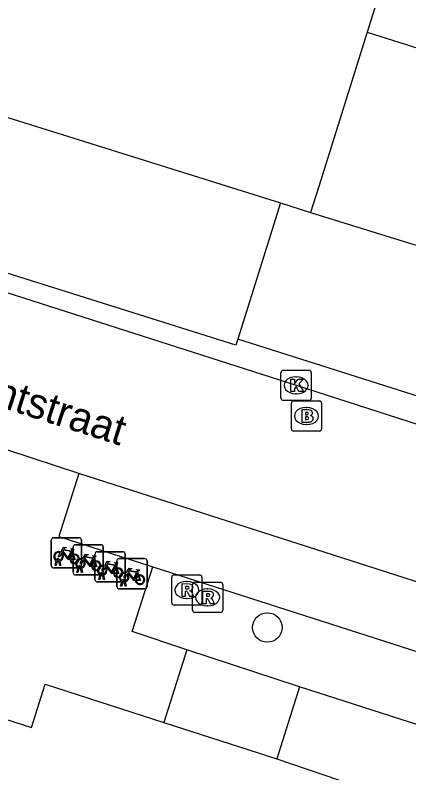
# Model space of a CAD drawing. Extents: x 160676 to 161153, y 383244 to 383713.
# Drawn here: x 160900.48 to 160913.52, y 383387.79 to 383412.86 of the extents above; entities that cross this region are included whole.
import ezdxf

# ---------------------------------------------------------------- set-up
doc = ezdxf.new("R2010")
doc.units = 0
for name, color, linetype in [('IMGEO_Boom', 7, 'Continuous'), ('IMGEO_Brandkraan', 7, 'Continuous'), ('IMGEO_Fietsenrek', 7, 'Continuous'), ('IMGEO_Hek', 7, 'Continuous'), ('IMGEO_Kolk', 7, 'Continuous'), ('IMGEO_Openbare_ruimte_label', 7, 'Continuous'), ('IMGEO_Pand', 7, 'Continuous'), ('IMGEO_Parkeervlak_open', 7, 'Continuous'), ('IMGEO_Rijbaan_lokaal_open', 7, 'Continuous'), ('IMGEO_Rioolput', 7, 'Continuous'), ('IMGEO_Voetpad_op_trap', 7, 'Continuous'), ('IMGEO_Voetpad_open', 7, 'Continuous')]:
    doc.layers.add(name, color=color, linetype=linetype)

msp = doc.modelspace()

# ---------------------------------------------------------------- linework, layer by layer
at = {"layer": 'IMGEO_Boom'}
msp.add_circle((160908.826, 383392.602), 0.489, dxfattribs=at)
at = {"layer": 'IMGEO_Brandkraan'}
for p, q in [((160909.699, 383400.1), (160910.551, 383400.1)), ((160909.624, 383399.174), (160909.624, 383400.026)), ((160910.112, 383399.88), (160910.137, 383399.88)), ((160910.625, 383400.026), (160910.625, 383399.174)), ((160910.551, 383399.1), (160909.699, 383399.1)), ((160910.135, 383399.32), (160910.11, 383399.32))]:
    msp.add_line(p, q, dxfattribs=at)
for points in [[(160909.699, 383400.1), (160910.551, 383400.1)], [(160909.624, 383399.174), (160909.624, 383400.026)], [(160910.625, 383400.026), (160910.625, 383399.174)], [(160909.972, 383399.8), (160909.972, 383399.4), (160910.185, 383399.4)], [(160910.203, 383399.8), (160909.972, 383399.8)], [(160910.151, 383399.719), (160910.097, 383399.719), (160910.097, 383399.643)], [(160910.097, 383399.643), (160910.15, 383399.643)], [(160910.159, 383399.567), (160910.097, 383399.567), (160910.097, 383399.486)], [(160910.097, 383399.486), (160910.159, 383399.486)], [(160910.551, 383399.1), (160909.699, 383399.1)]]:
    msp.add_lwpolyline(points, dxfattribs=at)
for centre, radius, start, end in [((160909.701, 383400.024), 0.0765, 91.552, 178.448), ((160909.701, 383400.024), 0.0765, 91.552, 178.448), ((160910.549, 383400.024), 0.0765, 1.552, 88.448), ((160910.549, 383400.024), 0.0765, 1.552, 88.448), ((160910.152, 383399.681), 0.0379, 267.8285, 90.9355), ((160910.207, 383399.655), 0.145, 59.4692, 91.5367), ((160910.232, 383399.702), 0.0922, 285.5137, 58.1501), ((160910.237, 383399.51), 0.105, 301.3115, 78.989), ((160910.16, 383399.526), 0.0404, 269.8759, 90.5077), ((160910.191, 383399.651), 0.251, 268.6676, 293.5347), ((160909.701, 383399.176), 0.0765, 181.552, 268.448), ((160909.701, 383399.176), 0.0765, 181.552, 268.448), ((160910.549, 383399.176), 0.0765, 271.552, 358.448), ((160910.549, 383399.176), 0.0765, 271.552, 358.448)]:
    msp.add_arc(centre, radius, start, end, dxfattribs=at)
for centre, major_axis, ratio, start_param, end_param in [((160910.111, 383399.6), (-0.387, 0.002), 0.722429, 4.712389, 7.853982), ((160910.136, 383399.6), (-0.39, 0.002), 0.717154, 1.570796, 4.712389)]:
    msp.add_ellipse(centre, major_axis=major_axis, ratio=ratio, start_param=start_param, end_param=end_param, dxfattribs=at)
at = {"layer": 'IMGEO_Fietsenrek'}
for p, q in [((160901.748, 383395.571), (160902.589, 383395.571)), ((160902.589, 383395.571), (160901.748, 383395.571)), ((160901.673, 383394.646), (160901.673, 383395.487)), ((160901.673, 383395.487), (160901.673, 383394.646)), ((160902.471, 383395.341), (160903.312, 383395.341)), ((160903.312, 383395.341), (160902.471, 383395.341)), ((160902.673, 383395.496), (160902.673, 383394.655)), ((160902.673, 383394.655), (160902.673, 383395.496)), ((160902.36, 383395.12), (160902.396, 383395.025)), ((160902.396, 383394.416), (160902.396, 383395.257)), ((160902.396, 383395.257), (160902.396, 383394.416)), ((160903.195, 383395.11), (160904.036, 383395.11)), ((160904.036, 383395.11), (160903.195, 383395.11)), ((160903.396, 383395.266), (160903.396, 383394.425)), ((160903.396, 383394.425), (160903.396, 383395.266)), ((160901.8, 383394.655), (160901.839, 383394.815)), ((160901.911, 383394.827), (160901.91, 383394.831)), ((160901.942, 383394.838), (160901.943, 383394.831)), ((160903.083, 383394.89), (160903.119, 383394.795)), ((160903.12, 383394.185), (160903.12, 383395.026)), ((160903.12, 383395.026), (160903.12, 383394.185)), ((160903.918, 383394.88), (160904.759, 383394.88)), ((160904.759, 383394.88), (160903.918, 383394.88)), ((160904.12, 383395.035), (160904.12, 383394.194)), ((160904.12, 383394.194), (160904.12, 383395.035)), ((160902.598, 383394.571), (160901.757, 383394.571)), ((160901.757, 383394.571), (160902.598, 383394.571)), ((160901.834, 383394.655), (160901.8, 383394.655)), ((160901.869, 383394.803), (160901.834, 383394.655)), ((160901.952, 383394.655), (160901.918, 383394.797)), ((160901.95, 383394.801), (160901.985, 383394.655)), ((160901.985, 383394.655), (160901.952, 383394.655)), ((160902.523, 383394.425), (160902.562, 383394.585)), ((160902.592, 383394.573), (160902.557, 383394.425)), ((160902.634, 383394.597), (160902.633, 383394.601)), ((160902.675, 383394.425), (160902.641, 383394.567)), ((160902.665, 383394.608), (160902.666, 383394.601)), ((160902.673, 383394.571), (160902.708, 383394.425)), ((160903.807, 383394.659), (160903.843, 383394.564)), ((160903.843, 383393.955), (160903.843, 383394.796)), ((160903.843, 383394.796), (160903.843, 383393.955)), ((160904.843, 383394.805), (160904.843, 383393.964)), ((160904.843, 383393.964), (160904.843, 383394.805)), ((160903.321, 383394.341), (160902.48, 383394.341)), ((160902.48, 383394.341), (160903.321, 383394.341)), ((160902.557, 383394.425), (160902.523, 383394.425)), ((160902.708, 383394.425), (160902.675, 383394.425)), ((160903.247, 383394.194), (160903.286, 383394.354)), ((160903.316, 383394.342), (160903.281, 383394.194)), ((160903.358, 383394.366), (160903.357, 383394.37)), ((160903.399, 383394.194), (160903.365, 383394.336)), ((160903.389, 383394.377), (160903.39, 383394.37)), ((160903.397, 383394.34), (160903.432, 383394.194)), ((160904.53, 383394.429), (160904.566, 383394.334)), ((160904.045, 383394.11), (160903.204, 383394.11)), ((160903.204, 383394.11), (160904.045, 383394.11)), ((160903.281, 383394.194), (160903.247, 383394.194)), ((160903.432, 383394.194), (160903.399, 383394.194)), ((160903.97, 383393.964), (160904.009, 383394.124)), ((160904.039, 383394.112), (160904.004, 383393.964)), ((160904.081, 383394.136), (160904.08, 383394.14)), ((160904.122, 383393.964), (160904.088, 383394.106)), ((160904.112, 383394.147), (160904.113, 383394.14)), ((160904.12, 383394.11), (160904.155, 383393.964)), ((160904.768, 383393.88), (160903.927, 383393.88)), ((160903.927, 383393.88), (160904.768, 383393.88)), ((160904.004, 383393.964), (160903.97, 383393.964)), ((160904.155, 383393.964), (160904.122, 383393.964))]:
    msp.add_line(p, q, dxfattribs=at)
for points in [[(160902.007, 383395.045), (160901.955, 383394.955), (160901.915, 383394.93), (160901.916, 383394.977), (160901.971, 383395.071)], [(160901.986, 383395.097), (160902.081, 383395.261), (160902.167, 383395.247), (160902.169, 383395.238), (160902.113, 383395.227), (160902.086, 383395.182), (160902.342, 383395.141)], [(160902.282, 383394.853), (160902.232, 383394.853), (160902.041, 383395.104), (160902.022, 383395.072)], [(160902.329, 383395.116), (160902.072, 383395.157), (160902.055, 383395.128), (160902.222, 383394.908), (160902.329, 383395.116)], [(160902.377, 383395.018), (160902.347, 383395.095), (160902.238, 383394.877), (160902.281, 383394.877)], [(160902.342, 383395.141), (160902.367, 383395.19), (160902.361, 383395.194), (160902.338, 383395.198), (160902.326, 383395.205), (160902.325, 383395.208), (160902.327, 383395.213), (160902.422, 383395.198), (160902.424, 383395.188), (160902.414, 383395.175), (160902.402, 383395.169), (160902.388, 383395.175), (160902.36, 383395.12)], [(160902.311, 383394.877), (160902.431, 383394.876), (160902.387, 383394.99)], [(160902.407, 383394.997), (160902.462, 383394.852), (160902.312, 383394.852)], [(160902.73, 383394.815), (160902.678, 383394.725), (160902.638, 383394.7), (160902.639, 383394.747), (160902.694, 383394.841)], [(160902.709, 383394.867), (160902.804, 383395.031), (160902.89, 383395.017), (160902.892, 383395.008), (160902.836, 383394.997), (160902.809, 383394.952), (160903.065, 383394.911)], [(160903.005, 383394.623), (160902.955, 383394.623), (160902.764, 383394.874), (160902.745, 383394.842)], [(160903.052, 383394.886), (160902.795, 383394.927), (160902.778, 383394.898), (160902.945, 383394.678), (160903.052, 383394.886)], [(160903.1, 383394.788), (160903.07, 383394.865), (160902.961, 383394.647), (160903.004, 383394.647)], [(160903.065, 383394.911), (160903.09, 383394.96), (160903.084, 383394.964), (160903.061, 383394.968), (160903.049, 383394.975), (160903.048, 383394.978), (160903.05, 383394.983), (160903.145, 383394.968), (160903.147, 383394.958), (160903.137, 383394.945), (160903.125, 383394.939), (160903.111, 383394.945), (160903.083, 383394.89)], [(160903.034, 383394.647), (160903.154, 383394.646), (160903.11, 383394.76)], [(160903.13, 383394.767), (160903.185, 383394.622), (160903.035, 383394.622)], [(160903.454, 383394.584), (160903.402, 383394.494), (160903.362, 383394.469), (160903.363, 383394.516), (160903.418, 383394.61)], [(160903.433, 383394.636), (160903.528, 383394.8), (160903.614, 383394.786), (160903.616, 383394.777), (160903.56, 383394.766), (160903.533, 383394.721), (160903.789, 383394.68)], [(160903.729, 383394.392), (160903.679, 383394.392), (160903.488, 383394.643), (160903.469, 383394.611)], [(160903.776, 383394.655), (160903.519, 383394.696), (160903.502, 383394.667), (160903.669, 383394.447), (160903.776, 383394.655)], [(160903.824, 383394.557), (160903.794, 383394.634), (160903.685, 383394.416), (160903.728, 383394.416)], [(160903.789, 383394.68), (160903.814, 383394.729), (160903.808, 383394.733), (160903.785, 383394.737), (160903.773, 383394.744), (160903.772, 383394.747), (160903.774, 383394.752), (160903.869, 383394.737), (160903.871, 383394.727), (160903.861, 383394.714), (160903.849, 383394.708), (160903.835, 383394.714), (160903.807, 383394.659)], [(160904.156, 383394.406), (160904.251, 383394.57), (160904.337, 383394.556), (160904.339, 383394.547), (160904.283, 383394.536), (160904.256, 383394.491), (160904.512, 383394.45)], [(160903.758, 383394.416), (160903.878, 383394.415), (160903.834, 383394.529)], [(160903.854, 383394.536), (160903.909, 383394.391), (160903.759, 383394.391)], [(160904.177, 383394.354), (160904.125, 383394.264), (160904.085, 383394.239), (160904.086, 383394.286), (160904.141, 383394.38)], [(160904.452, 383394.162), (160904.402, 383394.162), (160904.211, 383394.413), (160904.192, 383394.381)], [(160904.499, 383394.425), (160904.242, 383394.466), (160904.225, 383394.437), (160904.392, 383394.217), (160904.499, 383394.425)], [(160904.547, 383394.327), (160904.517, 383394.404), (160904.408, 383394.186), (160904.451, 383394.186)], [(160904.512, 383394.45), (160904.537, 383394.499), (160904.531, 383394.503), (160904.508, 383394.507), (160904.496, 383394.514), (160904.495, 383394.517), (160904.497, 383394.522), (160904.592, 383394.507), (160904.594, 383394.497), (160904.584, 383394.484), (160904.572, 383394.478), (160904.558, 383394.484), (160904.53, 383394.429)], [(160904.481, 383394.186), (160904.601, 383394.185), (160904.557, 383394.299)], [(160904.577, 383394.306), (160904.632, 383394.161), (160904.482, 383394.161)]]:
    msp.add_lwpolyline(points, dxfattribs=at)
for centre, radius, start, end in [((160901.751, 383395.493), 0.0779, 92.4484, 184.2845), ((160901.751, 383395.493), 0.0779, 92.4484, 184.2845), ((160902.595, 383395.493), 0.0779, 2.4484, 94.2845), ((160902.595, 383395.493), 0.0779, 2.4484, 94.2845), ((160902.474, 383395.263), 0.0779, 92.4484, 184.2845), ((160902.474, 383395.263), 0.0779, 92.4484, 184.2845), ((160903.318, 383395.263), 0.0779, 2.4484, 94.2845), ((160903.318, 383395.263), 0.0779, 2.4484, 94.2845), ((160901.913, 383394.956), 0.159, 62.6766, 242.1369), ((160901.913, 383394.956), 0.129, 63.3192, 238.903), ((160901.913, 383394.956), 0.159, 283.5766, 46.6042), ((160903.198, 383395.032), 0.0779, 92.4484, 184.2845), ((160903.198, 383395.032), 0.0779, 92.4484, 184.2845), ((160904.042, 383395.032), 0.0779, 2.4484, 94.2845), ((160904.042, 383395.032), 0.0779, 2.4484, 94.2845), ((160901.893, 383394.827), 0.0499, 12.8025, 158.6934), ((160901.893, 383394.827), 0.0174, 12.8025, 163.4502), ((160901.913, 383394.956), 0.129, 253.415, 269.0204), ((160901.913, 383394.956), 0.129, 283.6043, 43.4302), ((160902.44, 383394.872), 0.159, 113.3408, 178.3217), ((160902.44, 383394.872), 0.159, 187.0065, 105.7708), ((160902.44, 383394.872), 0.129, 113.923, 177.9556), ((160902.44, 383394.872), 0.129, 188.6715, 104.5883), ((160902.636, 383394.726), 0.159, 62.6766, 242.1369), ((160902.636, 383394.726), 0.129, 63.3192, 238.903), ((160902.636, 383394.726), 0.129, 283.6043, 43.4302), ((160902.636, 383394.726), 0.159, 283.5766, 46.6042), ((160903.921, 383394.802), 0.0779, 92.4484, 184.2845), ((160903.921, 383394.802), 0.0779, 92.4484, 184.2845), ((160904.765, 383394.802), 0.0779, 2.4484, 94.2845), ((160904.765, 383394.802), 0.0779, 2.4484, 94.2845), ((160901.751, 383394.649), 0.0779, 182.4484, 274.2845), ((160901.751, 383394.649), 0.0779, 182.4484, 274.2845), ((160901.913, 383394.956), 0.159, 253.9967, 271.7867), ((160902.616, 383394.597), 0.0499, 12.8025, 158.6934), ((160902.636, 383394.726), 0.159, 253.9967, 271.7867), ((160902.595, 383394.649), 0.0779, 272.4484, 4.2845), ((160902.595, 383394.649), 0.0779, 272.4484, 4.2845), ((160902.616, 383394.597), 0.0174, 12.8025, 163.4502), ((160902.636, 383394.726), 0.129, 253.415, 269.0204), ((160903.163, 383394.642), 0.159, 113.3408, 178.3217), ((160903.163, 383394.642), 0.159, 187.0065, 105.7708), ((160903.163, 383394.642), 0.129, 113.923, 177.9556), ((160903.163, 383394.642), 0.129, 188.6715, 104.5883), ((160903.36, 383394.495), 0.159, 62.6766, 242.1369), ((160903.36, 383394.495), 0.129, 63.3192, 238.903), ((160903.36, 383394.495), 0.129, 283.6043, 43.4302), ((160903.36, 383394.495), 0.159, 283.5766, 46.6042), ((160903.887, 383394.411), 0.159, 187.0065, 105.7708), ((160902.474, 383394.419), 0.0779, 182.4484, 274.2845), ((160902.474, 383394.419), 0.0779, 182.4484, 274.2845), ((160903.34, 383394.366), 0.0499, 12.8025, 158.6934), ((160903.36, 383394.495), 0.159, 253.9967, 271.7867), ((160903.318, 383394.419), 0.0779, 272.4484, 4.2845), ((160903.318, 383394.419), 0.0779, 272.4484, 4.2845), ((160903.34, 383394.366), 0.0174, 12.8025, 163.4502), ((160903.36, 383394.495), 0.129, 253.415, 269.0204), ((160903.887, 383394.411), 0.159, 113.3408, 178.3217), ((160903.887, 383394.411), 0.129, 113.923, 177.9556), ((160903.887, 383394.411), 0.129, 188.6715, 104.5883), ((160904.083, 383394.265), 0.159, 62.6766, 242.1369), ((160904.083, 383394.265), 0.129, 63.3192, 238.903), ((160904.083, 383394.265), 0.129, 283.6043, 43.4302), ((160904.083, 383394.265), 0.159, 283.5766, 46.6042), ((160904.61, 383394.181), 0.159, 113.3408, 178.3217), ((160904.61, 383394.181), 0.159, 187.0065, 105.7708), ((160904.61, 383394.181), 0.129, 188.6715, 104.5883), ((160903.198, 383394.188), 0.0779, 182.4484, 274.2845), ((160903.198, 383394.188), 0.0779, 182.4484, 274.2845), ((160904.063, 383394.136), 0.0499, 12.8025, 158.6934), ((160904.083, 383394.265), 0.159, 253.9967, 271.7867), ((160904.042, 383394.188), 0.0779, 272.4484, 4.2845), ((160904.042, 383394.188), 0.0779, 272.4484, 4.2845), ((160904.063, 383394.136), 0.0174, 12.8025, 163.4502), ((160904.083, 383394.265), 0.129, 253.415, 269.0204), ((160904.61, 383394.181), 0.129, 113.923, 177.9556), ((160903.921, 383393.958), 0.0779, 182.4484, 274.2845), ((160903.921, 383393.958), 0.0779, 182.4484, 274.2845), ((160904.765, 383393.958), 0.0779, 272.4484, 4.2845), ((160904.765, 383393.958), 0.0779, 272.4484, 4.2845)]:
    msp.add_arc(centre, radius, start, end, dxfattribs=at)
at = {"layer": 'IMGEO_Hek'}
msp.add_lwpolyline([(160947.221, 383389.66), (160907.851, 383402.14)], dxfattribs=at)
at = {"layer": 'IMGEO_Kolk'}
for p, q in [((160909.355, 383401.115), (160910.207, 383401.115)), ((160909.28, 383400.189), (160909.28, 383401.041)), ((160909.768, 383400.895), (160909.793, 383400.895)), ((160910.281, 383401.041), (160910.281, 383400.189)), ((160909.791, 383400.335), (160909.766, 383400.335)), ((160910.207, 383400.115), (160909.355, 383400.115))]:
    msp.add_line(p, q, dxfattribs=at)
for points in [[(160909.355, 383401.115), (160910.207, 383401.115)], [(160909.28, 383400.189), (160909.28, 383401.041)], [(160910.281, 383401.041), (160910.281, 383400.189)], [(160909.601, 383400.815), (160909.724, 383400.815), (160909.724, 383400.664), (160909.854, 383400.815), (160910.018, 383400.815), (160909.872, 383400.664), (160910.025, 383400.415), (160909.873, 383400.415), (160909.788, 383400.579), (160909.724, 383400.512), (160909.724, 383400.415), (160909.601, 383400.415), (160909.601, 383400.815)], [(160910.207, 383400.115), (160909.355, 383400.115)]]:
    msp.add_lwpolyline(points, dxfattribs=at)
for centre, start, end in [((160909.357, 383401.039), 91.552, 178.448), ((160909.357, 383401.039), 91.552, 178.448), ((160910.205, 383401.039), 1.552, 88.448), ((160910.205, 383401.039), 1.552, 88.448), ((160909.357, 383400.191), 181.552, 268.448), ((160909.357, 383400.191), 181.552, 268.448), ((160910.205, 383400.191), 271.552, 358.448), ((160910.205, 383400.191), 271.552, 358.448)]:
    msp.add_arc(centre, 0.0765, start, end, dxfattribs=at)
for centre, major_axis, ratio, start_param, end_param in [((160909.767, 383400.615), (-0.387, 0.002), 0.722429, 4.712389, 7.853982), ((160909.792, 383400.615), (-0.39, 0.002), 0.717154, 1.570796, 4.712389)]:
    msp.add_ellipse(centre, major_axis=major_axis, ratio=ratio, start_param=start_param, end_param=end_param, dxfattribs=at)
at = {"layer": 'IMGEO_Pand'}
for points in [[(160907.851, 383402.14), (160907.79, 383401.946), (160898.585, 383404.834), (160900.061, 383409.537), (160909.266, 383406.649)], [(160909.266, 383406.649), (160907.851, 383402.14)], [(160886.606, 383395.503), (160896.283, 383392.391), (160895.823, 383390.963), (160901.015, 383389.295), (160901.475, 383390.722), (160905.053, 383389.568), (160905.398, 383389.462)], [(160905.398, 383389.462), (160909.143, 383388.26)], [(160909.143, 383388.26), (160911.188, 383387.556), (160910.671, 383385.909)]]:
    msp.add_lwpolyline(points, dxfattribs=at)
at = {"layer": 'IMGEO_Parkeervlak_open'}
for points in [[(160913.38, 383416.284), (160912.129, 383412.296)], [(160909.266, 383406.649), (160910.259, 383406.337)], [(160947.221, 383389.66), (160907.851, 383402.14)], [(160905.032, 383394.612), (160936.244, 383384.606), (160952.13, 383379.495)]]:
    msp.add_lwpolyline(points, dxfattribs=at)
at = {"layer": 'IMGEO_Rijbaan_lokaal_open'}
for points in [[(160912.129, 383412.296), (160910.529, 383407.197), (160910.259, 383406.337)], [(160912.129, 383412.296), (160949.567, 383400.481)], [(160887.438, 383407.737), (160890.968, 383406.604), (160893.121, 383405.949), (160909.781, 383400.615), (160922.621, 383396.479), (160938.323, 383391.448), (160946.431, 383388.877)], [(160910.259, 383406.337), (160952.446, 383393.288)], [(160902.588, 383397.698), (160899.445, 383398.723)], [(160953.275, 383381.428), (160937.803, 383386.409), (160902.588, 383397.698)]]:
    msp.add_lwpolyline(points, dxfattribs=at)
at = {"layer": 'IMGEO_Rioolput'}
for p, q in [((160905.737, 383394.342), (160906.589, 383394.342)), ((160905.662, 383393.416), (160905.662, 383394.268)), ((160906.15, 383394.122), (160906.175, 383394.122)), ((160906.424, 383394.098), (160907.276, 383394.098)), ((160906.663, 383394.268), (160906.663, 383393.416)), ((160906.349, 383393.172), (160906.349, 383394.024)), ((160906.837, 383393.878), (160906.862, 383393.878)), ((160907.35, 383394.024), (160907.35, 383393.172)), ((160906.173, 383393.562), (160906.148, 383393.562)), ((160906.589, 383393.342), (160905.737, 383393.342)), ((160906.86, 383393.318), (160906.835, 383393.318)), ((160907.276, 383393.098), (160906.424, 383393.098))]:
    msp.add_line(p, q, dxfattribs=at)
for points in [[(160905.737, 383394.342), (160906.589, 383394.342)], [(160905.662, 383393.416), (160905.662, 383394.268)], [(160906.424, 383394.098), (160907.276, 383394.098)], [(160906.663, 383394.268), (160906.663, 383393.416)], [(160906.251, 383394.04), (160905.999, 383394.042), (160905.999, 383393.642)], [(160906.177, 383393.961), (160906.123, 383393.961), (160906.123, 383393.88)], [(160906.123, 383393.88), (160906.175, 383393.88)], [(160906.349, 383393.172), (160906.349, 383394.024)], [(160907.35, 383394.024), (160907.35, 383393.172)], [(160905.999, 383393.642), (160906.123, 383393.642), (160906.123, 383393.804), (160906.134, 383393.804)], [(160906.181, 383393.775), (160906.252, 383393.642), (160906.392, 383393.642), (160906.327, 383393.768)], [(160906.938, 383393.796), (160906.686, 383393.798), (160906.686, 383393.398)], [(160906.686, 383393.398), (160906.81, 383393.398), (160906.81, 383393.56), (160906.821, 383393.56)], [(160906.864, 383393.717), (160906.81, 383393.717), (160906.81, 383393.636)], [(160906.81, 383393.636), (160906.862, 383393.636)], [(160906.589, 383393.342), (160905.737, 383393.342)], [(160906.868, 383393.531), (160906.939, 383393.398), (160907.079, 383393.398), (160907.014, 383393.524)], [(160907.276, 383393.098), (160906.424, 383393.098)]]:
    msp.add_lwpolyline(points, dxfattribs=at)
for centre, radius, start, end in [((160905.739, 383394.266), 0.0765, 91.552, 178.448), ((160905.739, 383394.266), 0.0765, 91.552, 178.448), ((160906.587, 383394.266), 0.0765, 1.552, 88.448), ((160906.587, 383394.266), 0.0765, 1.552, 88.448), ((160906.426, 383394.022), 0.0765, 91.552, 178.448), ((160906.426, 383394.022), 0.0765, 91.552, 178.448), ((160907.274, 383394.022), 0.0765, 1.552, 88.448), ((160907.274, 383394.022), 0.0765, 1.552, 88.448), ((160906.159, 383394.069), 0.19, 274.7715, 282.9687), ((160906.183, 383393.865), 0.0964, 77.0061, 93.1865), ((160906.197, 383393.922), 0.0378, 276.6634, 79.6772), ((160906.25, 383393.93), 0.109, 350.3612, 89.416), ((160906.248, 383393.93), 0.112, 277.5842, 350.9817), ((160906.232, 383393.715), 0.108, 29.5134, 73.7905), ((160906.133, 383393.751), 0.0533, 26.0293, 88.6989), ((160906.82, 383393.507), 0.0533, 26.0293, 88.6989), ((160906.846, 383393.825), 0.19, 274.7715, 282.9687), ((160906.87, 383393.621), 0.0964, 77.0061, 93.1865), ((160906.884, 383393.678), 0.0378, 276.6634, 79.6772), ((160906.937, 383393.686), 0.109, 350.3612, 89.416), ((160906.935, 383393.686), 0.112, 277.5842, 350.9817), ((160906.919, 383393.471), 0.108, 29.5134, 73.7905), ((160905.739, 383393.418), 0.0765, 181.552, 268.448), ((160905.739, 383393.418), 0.0765, 181.552, 268.448), ((160906.587, 383393.418), 0.0765, 271.552, 358.448), ((160906.587, 383393.418), 0.0765, 271.552, 358.448), ((160906.426, 383393.174), 0.0765, 181.552, 268.448), ((160906.426, 383393.174), 0.0765, 181.552, 268.448), ((160907.274, 383393.174), 0.0765, 271.552, 358.448), ((160907.274, 383393.174), 0.0765, 271.552, 358.448)]:
    msp.add_arc(centre, radius, start, end, dxfattribs=at)
for centre, major_axis, ratio, start_param, end_param in [((160906.149, 383393.842), (-0.387, 0.002), 0.722429, 4.712389, 7.853982), ((160906.174, 383393.842), (-0.39, 0.002), 0.717154, 1.570796, 4.712389), ((160906.836, 383393.598), (-0.387, 0.002), 0.722429, 4.712389, 7.853982), ((160906.861, 383393.598), (-0.39, 0.002), 0.717154, 1.570796, 4.712389)]:
    msp.add_ellipse(centre, major_axis=major_axis, ratio=ratio, start_param=start_param, end_param=end_param, dxfattribs=at)
at = {"layer": 'IMGEO_Voetpad_op_trap'}
msp.add_lwpolyline([(160909.89, 383390.636), (160906.167, 383391.864)], dxfattribs=at)
at = {"layer": 'IMGEO_Voetpad_open'}
for points in [[(160902.588, 383397.698), (160901.917, 383395.611), (160905.032, 383394.612)], [(160906.167, 383391.864), (160904.349, 383392.464), (160905.032, 383394.612)], [(160906.167, 383391.864), (160905.398, 383389.462)], [(160909.89, 383390.636), (160909.143, 383388.26)], [(160942.548, 383380.163), (160909.89, 383390.636)]]:
    msp.add_lwpolyline(points, dxfattribs=at)

# ---------------------------------------------------------------- texts
at = {"layer": 'IMGEO_Openbare_ruimte_label'}
msp.add_text('Lichtstraat', height=1, rotation=342.1811, dxfattribs=at).set_placement((160898.073, 383400.507))

doc.saveas('drawing.dxf')
